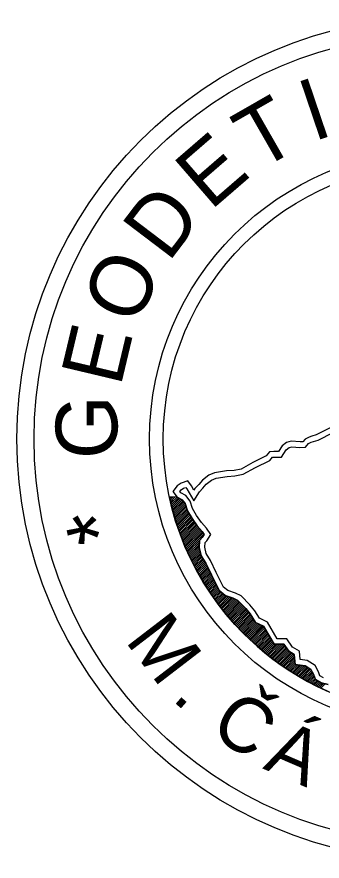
# Model space of a CAD drawing. Extents: x -757891 to -747391, y -1166581 to -1159156.
# Drawn here: x -749255.1 to -749107, y -1163767.5 to -1163357.6 of the extents above; entities that cross this region are included whole.
import ezdxf

# ---------------------------------------------------------------- set-up
doc = ezdxf.new("R2010")
doc.units = 0
doc.layers.add('Vrstva 63', color=7, linetype='Continuous')

msp = doc.modelspace()

# ---------------------------------------------------------------- linework, layer by layer
at = {"layer": 'Vrstva 63'}
for p, q in [((-749177.33, -1163590.69), (-749181.06, -1163590.66)), ((-749177.33, -1163590.69), (-749181.06, -1163590.66)), ((-749181.05, -1163590.67), (-749181.04, -1163590.66)), ((-749180.89, -1163591.44), (-749180.11, -1163590.67)), ((-749180.71, -1163592.21), (-749179.18, -1163590.67)), ((-749180.54, -1163592.97), (-749178.25, -1163590.68)), ((-749180.36, -1163593.73), (-749177.32, -1163590.69)), ((-749180.18, -1163594.49), (-749176.7, -1163591.02)), ((-749179.99, -1163595.24), (-749176.09, -1163591.34)), ((-749179.8, -1163595.99), (-749175.47, -1163591.67)), ((-749179.6, -1163596.73), (-749174.86, -1163591.99)), ((-749179.4, -1163597.47), (-749174.45, -1163592.53)), ((-749179.2, -1163598.21), (-749174.05, -1163593.06)), ((-749179, -1163598.95), (-749173.65, -1163593.6)), ((-749178.79, -1163599.68), (-749173.32, -1163594.21)), ((-749178.58, -1163600.4), (-749173.1, -1163594.93)), ((-749178.36, -1163601.13), (-749172.88, -1163595.65)), ((-749178.14, -1163601.85), (-749172.66, -1163596.37)), ((-749177.92, -1163602.57), (-749172.44, -1163597.09)), ((-749177.69, -1163603.28), (-749172.14, -1163597.73)), ((-749177.46, -1163603.99), (-749171.79, -1163598.32)), ((-749177.23, -1163604.7), (-749171.44, -1163598.91)), ((-749177, -1163605.4), (-749171.09, -1163599.5)), ((-749176.76, -1163606.1), (-749170.74, -1163600.09)), ((-749176.52, -1163606.8), (-749170.39, -1163600.67)), ((-749176.27, -1163607.49), (-749170.03, -1163601.26)), ((-749176.02, -1163608.18), (-749169.65, -1163601.81)), ((-749175.77, -1163608.87), (-749169.26, -1163602.36)), ((-749175.52, -1163609.56), (-749168.87, -1163602.91)), ((-749175.26, -1163610.24), (-749168.49, -1163603.47)), ((-749175, -1163610.92), (-749168.1, -1163604.02)), ((-749174.73, -1163611.59), (-749167.71, -1163604.57)), ((-749174.47, -1163612.27), (-749167.28, -1163605.08)), ((-749174.2, -1163612.93), (-749166.83, -1163605.57)), ((-749173.92, -1163613.6), (-749166.38, -1163606.06)), ((-749173.65, -1163614.26), (-749165.93, -1163606.55)), ((-749173.37, -1163614.93), (-749165.48, -1163607.04)), ((-749173.09, -1163615.58), (-749165.04, -1163607.54)), ((-749172.8, -1163616.24), (-749164.67, -1163608.11)), ((-749172.51, -1163616.89), (-749164.3, -1163608.68)), ((-749172.22, -1163617.54), (-749165.73, -1163611.04)), ((-749171.93, -1163618.19), (-749166.44, -1163612.7)), ((-749171.63, -1163618.83), (-749166.49, -1163613.69)), ((-749171.34, -1163619.47), (-749166.55, -1163614.68)), ((-749171.03, -1163620.11), (-749166.49, -1163615.57)), ((-749170.73, -1163620.74), (-749166.33, -1163616.34)), ((-749170.42, -1163621.37), (-749166.17, -1163617.12)), ((-749170.11, -1163622), (-749166.01, -1163617.9)), ((-749169.8, -1163622.63), (-749165.84, -1163618.67)), ((-749169.48, -1163623.25), (-749165.62, -1163619.39)), ((-749169.17, -1163623.88), (-749165.25, -1163619.96)), ((-749168.85, -1163624.49), (-749164.88, -1163620.53)), ((-749168.52, -1163625.11), (-749164.51, -1163621.1)), ((-749168.2, -1163625.72), (-749164.14, -1163621.66)), ((-749167.87, -1163626.33), (-749163.76, -1163622.23)), ((-749167.54, -1163626.94), (-749163.39, -1163622.8)), ((-749167.2, -1163627.55), (-749163.09, -1163623.44)), ((-749166.86, -1163628.15), (-749162.79, -1163624.08)), ((-749166.52, -1163628.75), (-749162.49, -1163624.71)), ((-749166.18, -1163629.35), (-749162.19, -1163625.35)), ((-749165.84, -1163629.94), (-749161.89, -1163625.99)), ((-749165.49, -1163630.54), (-749161.59, -1163626.63)), ((-749165.14, -1163631.12), (-749161.28, -1163627.27)), ((-749164.79, -1163631.71), (-749160.98, -1163627.91)), ((-749164.43, -1163632.3), (-749160.68, -1163628.54)), ((-749164.08, -1163632.88), (-749160.37, -1163629.17)), ((-749163.72, -1163633.46), (-749160.06, -1163629.8)), ((-749163.35, -1163634.04), (-749159.74, -1163630.42)), ((-749162.99, -1163634.61), (-749159.43, -1163631.05)), ((-749162.62, -1163635.18), (-749159.12, -1163631.68)), ((-749162.25, -1163635.75), (-749158.81, -1163632.31)), ((-749161.88, -1163636.32), (-749158.5, -1163632.93)), ((-749161.51, -1163636.88), (-749158.18, -1163633.56)), ((-749161.13, -1163637.45), (-749157.87, -1163634.19)), ((-749160.75, -1163638.01), (-749157.56, -1163634.82)), ((-749160.37, -1163638.56), (-749157.25, -1163635.44)), ((-749159.98, -1163639.12), (-749156.93, -1163636.07)), ((-749159.59, -1163639.67), (-749156.44, -1163636.51)), ((-749159.2, -1163640.22), (-749155.91, -1163636.92)), ((-749158.81, -1163640.77), (-749155.37, -1163637.33)), ((-749158.42, -1163641.31), (-749154.84, -1163637.74)), ((-749158.02, -1163641.85), (-749154.31, -1163638.14)), ((-749157.62, -1163642.39), (-749153.73, -1163638.5)), ((-749157.22, -1163642.93), (-749153.03, -1163638.74)), ((-749156.82, -1163643.47), (-749152.33, -1163638.98)), ((-749156.41, -1163644), (-749151.63, -1163639.22)), ((-749156, -1163644.53), (-749150.93, -1163639.46)), ((-749155.59, -1163645.06), (-749150.23, -1163639.7)), ((-749155.18, -1163645.59), (-749149.59, -1163640)), ((-749154.76, -1163646.11), (-749148.97, -1163640.32)), ((-749154.34, -1163646.63), (-749148.35, -1163640.64)), ((-749153.92, -1163647.15), (-749147.76, -1163640.99)), ((-749153.5, -1163647.66), (-749147.29, -1163641.46)), ((-749153.07, -1163648.18), (-749146.83, -1163641.93)), ((-749152.64, -1163648.69), (-749146.36, -1163642.41)), ((-749152.21, -1163649.2), (-749145.9, -1163642.88)), ((-749151.78, -1163649.71), (-749145.43, -1163643.35)), ((-749151.35, -1163650.21), (-749144.96, -1163643.83)), ((-749150.91, -1163650.71), (-749144.5, -1163644.3)), ((-749150.47, -1163651.21), (-749144.03, -1163644.77)), ((-749150.03, -1163651.71), (-749143.61, -1163645.29)), ((-749149.58, -1163652.21), (-749143.18, -1163645.8)), ((-749149.14, -1163652.7), (-749142.75, -1163646.31)), ((-749148.69, -1163653.19), (-749142.33, -1163646.83)), ((-749148.24, -1163653.68), (-749141.9, -1163647.34)), ((-749147.78, -1163654.16), (-749141.53, -1163647.91)), ((-749147.33, -1163654.65), (-749141.16, -1163648.48)), ((-749146.87, -1163655.13), (-749140.8, -1163649.06)), ((-749146.41, -1163655.61), (-749140.44, -1163649.64)), ((-749145.95, -1163656.08), (-749140.08, -1163650.22)), ((-749145.48, -1163656.56), (-749139.72, -1163650.79)), ((-749145.01, -1163657.03), (-749139.35, -1163651.37)), ((-749144.54, -1163657.5), (-749138.82, -1163651.77)), ((-749144.07, -1163657.97), (-749138.19, -1163652.08)), ((-749143.6, -1163658.43), (-749137.56, -1163652.39)), ((-749143.12, -1163658.89), (-749136.92, -1163652.7)), ((-749142.64, -1163659.35), (-749136.29, -1163653.01)), ((-749142.16, -1163659.81), (-749135.66, -1163653.32)), ((-749141.67, -1163660.27), (-749135.2, -1163653.79)), ((-749141.19, -1163660.72), (-749134.85, -1163654.38)), ((-749140.7, -1163661.17), (-749134.5, -1163654.97)), ((-749140.21, -1163661.62), (-749134.15, -1163655.56)), ((-749139.71, -1163662.07), (-749133.8, -1163656.15)), ((-749139.22, -1163662.51), (-749133.45, -1163656.74)), ((-749138.72, -1163662.95), (-749133.1, -1163657.33)), ((-749138.22, -1163663.39), (-749132.75, -1163657.92)), ((-749137.72, -1163663.83), (-749132.4, -1163658.5)), ((-749137.21, -1163664.26), (-749132.04, -1163659.09)), ((-749136.71, -1163664.69), (-749131.69, -1163659.68)), ((-749136.2, -1163665.12), (-749131.34, -1163660.27)), ((-749135.68, -1163665.55), (-749130.99, -1163660.86)), ((-749135.17, -1163665.98), (-749130.64, -1163661.45)), ((-749134.65, -1163666.4), (-749130.29, -1163662.04)), ((-749134.13, -1163666.82), (-749129.49, -1163662.17)), ((-749133.61, -1163667.24), (-749128.54, -1163662.17)), ((-749133.09, -1163667.65), (-749127.6, -1163662.16)), ((-749132.56, -1163668.07), (-749126.65, -1163662.15)), ((-749132.03, -1163668.48), (-749125.7, -1163662.15)), ((-749131.5, -1163668.88), (-749125.19, -1163662.58)), ((-749130.97, -1163669.29), (-749124.82, -1163663.14)), ((-749130.43, -1163669.69), (-749124.45, -1163663.71)), ((-749129.89, -1163670.1), (-749124.07, -1163664.27)), ((-749129.35, -1163670.49), (-749123.7, -1163664.84)), ((-749128.81, -1163670.89), (-749123.32, -1163665.4)), ((-749128.26, -1163671.28), (-749122.8, -1163665.82)), ((-749127.72, -1163671.68), (-749122.2, -1163666.16)), ((-749127.17, -1163672.06), (-749121.59, -1163666.49)), ((-749126.61, -1163672.45), (-749120.99, -1163666.82)), ((-749126.06, -1163672.84), (-749120.47, -1163667.24)), ((-749125.5, -1163673.22), (-749120.39, -1163668.1)), ((-749124.94, -1163673.6), (-749120.31, -1163668.96)), ((-749124.38, -1163673.97), (-749120.23, -1163669.82)), ((-749123.81, -1163674.35), (-749120.15, -1163670.68)), ((-749123.25, -1163674.72), (-749120.07, -1163671.54)), ((-749122.68, -1163675.09), (-749119.59, -1163672.01)), ((-749122.1, -1163675.46), (-749118.78, -1163672.13)), ((-749121.53, -1163675.82), (-749117.97, -1163672.26)), ((-749120.95, -1163676.18), (-749117.15, -1163672.39)), ((-749120.37, -1163676.54), (-749116.34, -1163672.51)), ((-749119.79, -1163676.9), (-749115.53, -1163672.64)), ((-749119.2, -1163677.25), (-749114.86, -1163672.91)), ((-749118.61, -1163677.61), (-749114.28, -1163673.27)), ((-749118.02, -1163677.95), (-749113.7, -1163673.63)), ((-749117.43, -1163678.3), (-749113.12, -1163673.98)), ((-749116.84, -1163678.65), (-749112.53, -1163674.34)), ((-749116.24, -1163678.99), (-749112.15, -1163674.9)), ((-749115.64, -1163679.33), (-749111.83, -1163675.51)), ((-749115.03, -1163679.66), (-749111.5, -1163676.13)), ((-749114.43, -1163680), (-749111.17, -1163676.74)), ((-749113.82, -1163680.33), (-749110.9, -1163677.4)), ((-749113.21, -1163680.65), (-749110.62, -1163678.07)), ((-749112.6, -1163680.98), (-749110.35, -1163678.74)), ((-749111.98, -1163681.3), (-749110.04, -1163679.36)), ((-749111.36, -1163681.62), (-749109.44, -1163679.7)), ((-749110.74, -1163681.94), (-749108.85, -1163680.05)), ((-749110.11, -1163682.26), (-749108.25, -1163680.4)), ((-749109.49, -1163682.57), (-749107.66, -1163680.74)), ((-749108.86, -1163682.88), (-749106.99, -1163681.01)), ((-749108.22, -1163683.18), (-749106.23, -1163681.19)), ((-749107.59, -1163683.49), (-749105.46, -1163681.36))]:
    msp.add_line(p, q, dxfattribs=at)
for points in [[(-749102.46, -1163556.82), (-749109.93, -1163560.58), (-749111.98, -1163561.18), (-749113.25, -1163561.59), (-749115.26, -1163562.66), (-749116.28, -1163563.92), (-749117.68, -1163563.96), (-749121.96, -1163563.66), (-749124.17, -1163564.29), (-749126.39, -1163565.86), (-749128.12, -1163568.63), (-749130.38, -1163568.61), (-749132.46, -1163568.79), (-749134.04, -1163570.78), (-749140.56, -1163574.01), (-749146.22, -1163577.15), (-749149.65, -1163577.83), (-749153.33, -1163578.04), (-749159.14, -1163579), (-749161.95, -1163580.15), (-749165.03, -1163582.44), (-749166.84, -1163584.61), (-749168.65, -1163586.53), (-749169.16, -1163587.36), (-749170.4, -1163585.21), (-749172.13, -1163582.9), (-749175.4, -1163583.93), (-749177.3, -1163585.2), (-749179.36, -1163588.1), (-749177.33, -1163590.69), (-749174.86, -1163591.99), (-749173.41, -1163593.9), (-749172.35, -1163597.38), (-749170.1, -1163601.17), (-749167.59, -1163604.74), (-749165.1, -1163607.45), (-749164.19, -1163608.86), (-749165.09, -1163610.32), (-749166.4, -1163611.8), (-749166.57, -1163615.19), (-749165.73, -1163619.23), (-749163.4, -1163622.79), (-749160.72, -1163628.46), (-749156.89, -1163636.16), (-749153.93, -1163638.44), (-749150.07, -1163639.76), (-749147.86, -1163640.88), (-749144.05, -1163644.76), (-749141.82, -1163647.44), (-749139.23, -1163651.57), (-749135.41, -1163653.44), (-749130.21, -1163662.18), (-749125.48, -1163662.15), (-749123.19, -1163665.61), (-749120.48, -1163667.1), (-749120.03, -1163671.94), (-749115.22, -1163672.68), (-749112.41, -1163674.42), (-749111.17, -1163676.75), (-749110.12, -1163679.31), (-749107.35, -1163680.92), (-749104.06, -1163681.69)], [(-749106.35, -1163678.43), (-749108, -1163677.47), (-749108.76, -1163675.61), (-749110.4, -1163672.53), (-749114.29, -1163670.14), (-749117.58, -1163669.63), (-749117.96, -1163665.46), (-749121.33, -1163663.6), (-749124.05, -1163659.48), (-749128.7, -1163659.51), (-749133.53, -1163651.4), (-749137.38, -1163649.52), (-749139.66, -1163645.88), (-749142.07, -1163642.97), (-749146.27, -1163638.71), (-749149.03, -1163637.31), (-749152.66, -1163636.06), (-749154.78, -1163634.43), (-749158.33, -1163627.3), (-749161.08, -1163621.49), (-749163.23, -1163618.19), (-749163.9, -1163614.99), (-749163.79, -1163612.86), (-749162.95, -1163611.91), (-749161.04, -1163608.83), (-749163, -1163605.82), (-749165.51, -1163603.07), (-749167.87, -1163599.72), (-749169.9, -1163596.3), (-749171.01, -1163592.67), (-749173.1, -1163589.91), (-749175.59, -1163588.6), (-749176.05, -1163588.02), (-749175.42, -1163587.14), (-749174.24, -1163586.35), (-749173.13, -1163586), (-749172.62, -1163586.68), (-749169.24, -1163592.53), (-749166.53, -1163588.15), (-749164.85, -1163586.37), (-749163.19, -1163584.39), (-749160.64, -1163582.48), (-749158.41, -1163581.57), (-749153.04, -1163580.68), (-749149.32, -1163580.47), (-749145.29, -1163579.67), (-749139.33, -1163576.36), (-749132.32, -1163572.9), (-749131.09, -1163571.34), (-749130.28, -1163571.27), (-749126.66, -1163571.29), (-749124.42, -1163567.72), (-749123, -1163566.72), (-749121.68, -1163566.34), (-749117.73, -1163566.62), (-749114.98, -1163566.53), (-749113.54, -1163564.75), (-749112.21, -1163564.05), (-749111.2, -1163563.72), (-749108.95, -1163563.06), (-749101.54, -1163559.33)], [(-749104.06, -1163681.69), (-749107.35, -1163680.92), (-749110.12, -1163679.31), (-749111.17, -1163676.75), (-749112.41, -1163674.42), (-749115.22, -1163672.68), (-749120.03, -1163671.94), (-749120.48, -1163667.1), (-749123.19, -1163665.61), (-749125.48, -1163662.15), (-749130.21, -1163662.18), (-749135.41, -1163653.44), (-749139.23, -1163651.57), (-749141.82, -1163647.44), (-749144.05, -1163644.76), (-749147.86, -1163640.88), (-749150.07, -1163639.76), (-749153.93, -1163638.44), (-749156.89, -1163636.16), (-749160.72, -1163628.46), (-749163.4, -1163622.79), (-749165.73, -1163619.23), (-749166.57, -1163615.19), (-749166.4, -1163611.8), (-749165.09, -1163610.32), (-749164.19, -1163608.86), (-749165.1, -1163607.45), (-749167.59, -1163604.74), (-749170.1, -1163601.17), (-749172.35, -1163597.38), (-749173.41, -1163593.9), (-749174.86, -1163591.99), (-749177.33, -1163590.69)]]:
    msp.add_lwpolyline(points, dxfattribs=at)
for radius in [204.94, 196.63, 196.63, 140.55, 140.55, 133.91]:
    msp.add_circle((-749050.14, -1163562.53), radius, dxfattribs=at)
msp.add_arc((-749050.14, -1163562.53), 133.91, 192.1248, 329.9318, dxfattribs=at)

# ---------------------------------------------------------------- texts
for s, height, rotation, p in [('I', 29.89, 18.7306, (-749111.32, -1163418.28)), ('T', 29.89, 29.797, (-749137.87, -1163432.7)), ('E', 29.89, 40.8634, (-749161.16, -1163451.96)), ('D', 29.89, 52.7843, (-749181.61, -1163477.28)), ('O', 29.89, 65.5492, (-749197.19, -1163508.43)), ('E', 29.89, 76.6156, (-749204.84, -1163537.67)), ('G', 29.89, 89.3804, (-749206.51, -1163572.46)), ('*', 29.89, 103.0104, (-749199.77, -1163609.04)), ('M', 26.57, 307.5302, (-749202.99, -1163660.45)), ('Č', 26.57, 326.6696, (-749162.44, -1163705.16)), ('.', 26.57, 319.0138, (-749180.44, -1163688.93)), ('Á', 26.57, 336.6266, (-749136.09, -1163722.43))]:
    msp.add_text(s, height=height, rotation=rotation, dxfattribs=at).set_placement(p)

doc.saveas('drawing.dxf')
